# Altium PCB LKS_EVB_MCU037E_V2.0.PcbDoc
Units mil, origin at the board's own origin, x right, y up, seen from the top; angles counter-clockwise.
Board outline 1880 x 1275 mil, 2 copper layers (Top Layer, Bottom Layer); 40 components, 32 nets, 121 pads, 45 vias.
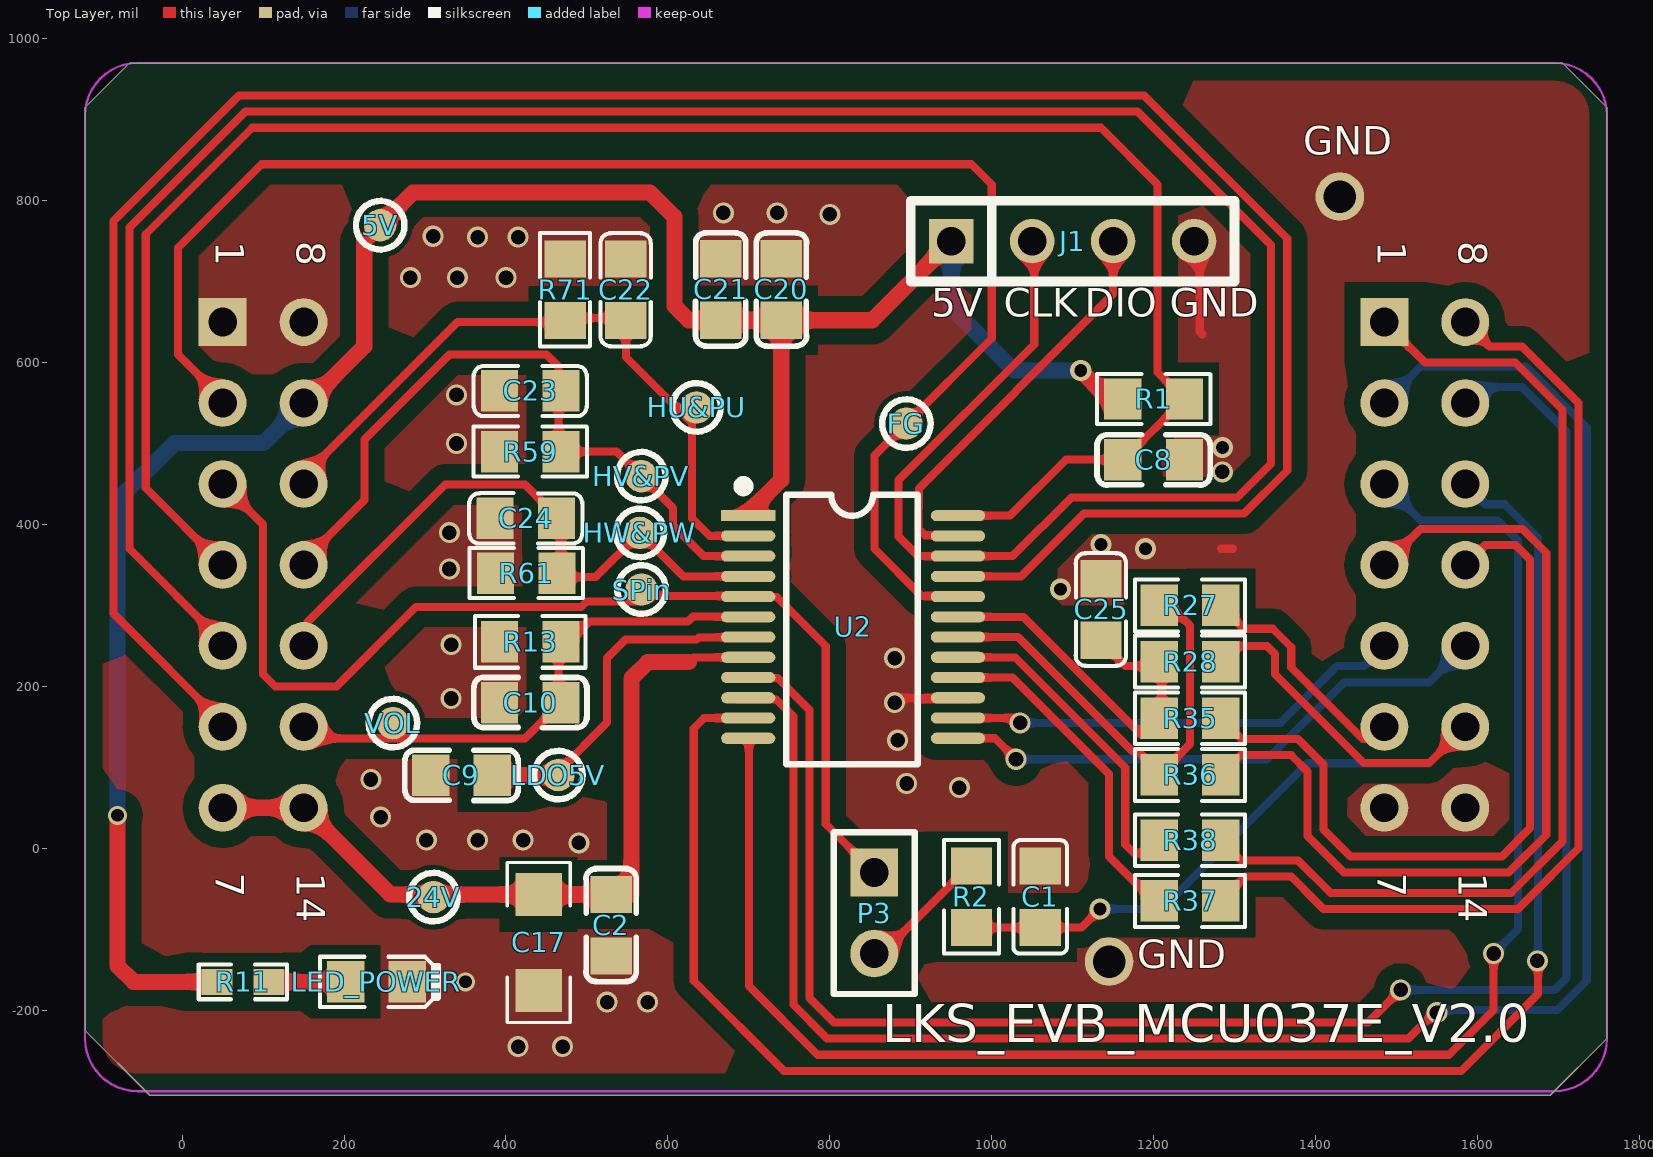
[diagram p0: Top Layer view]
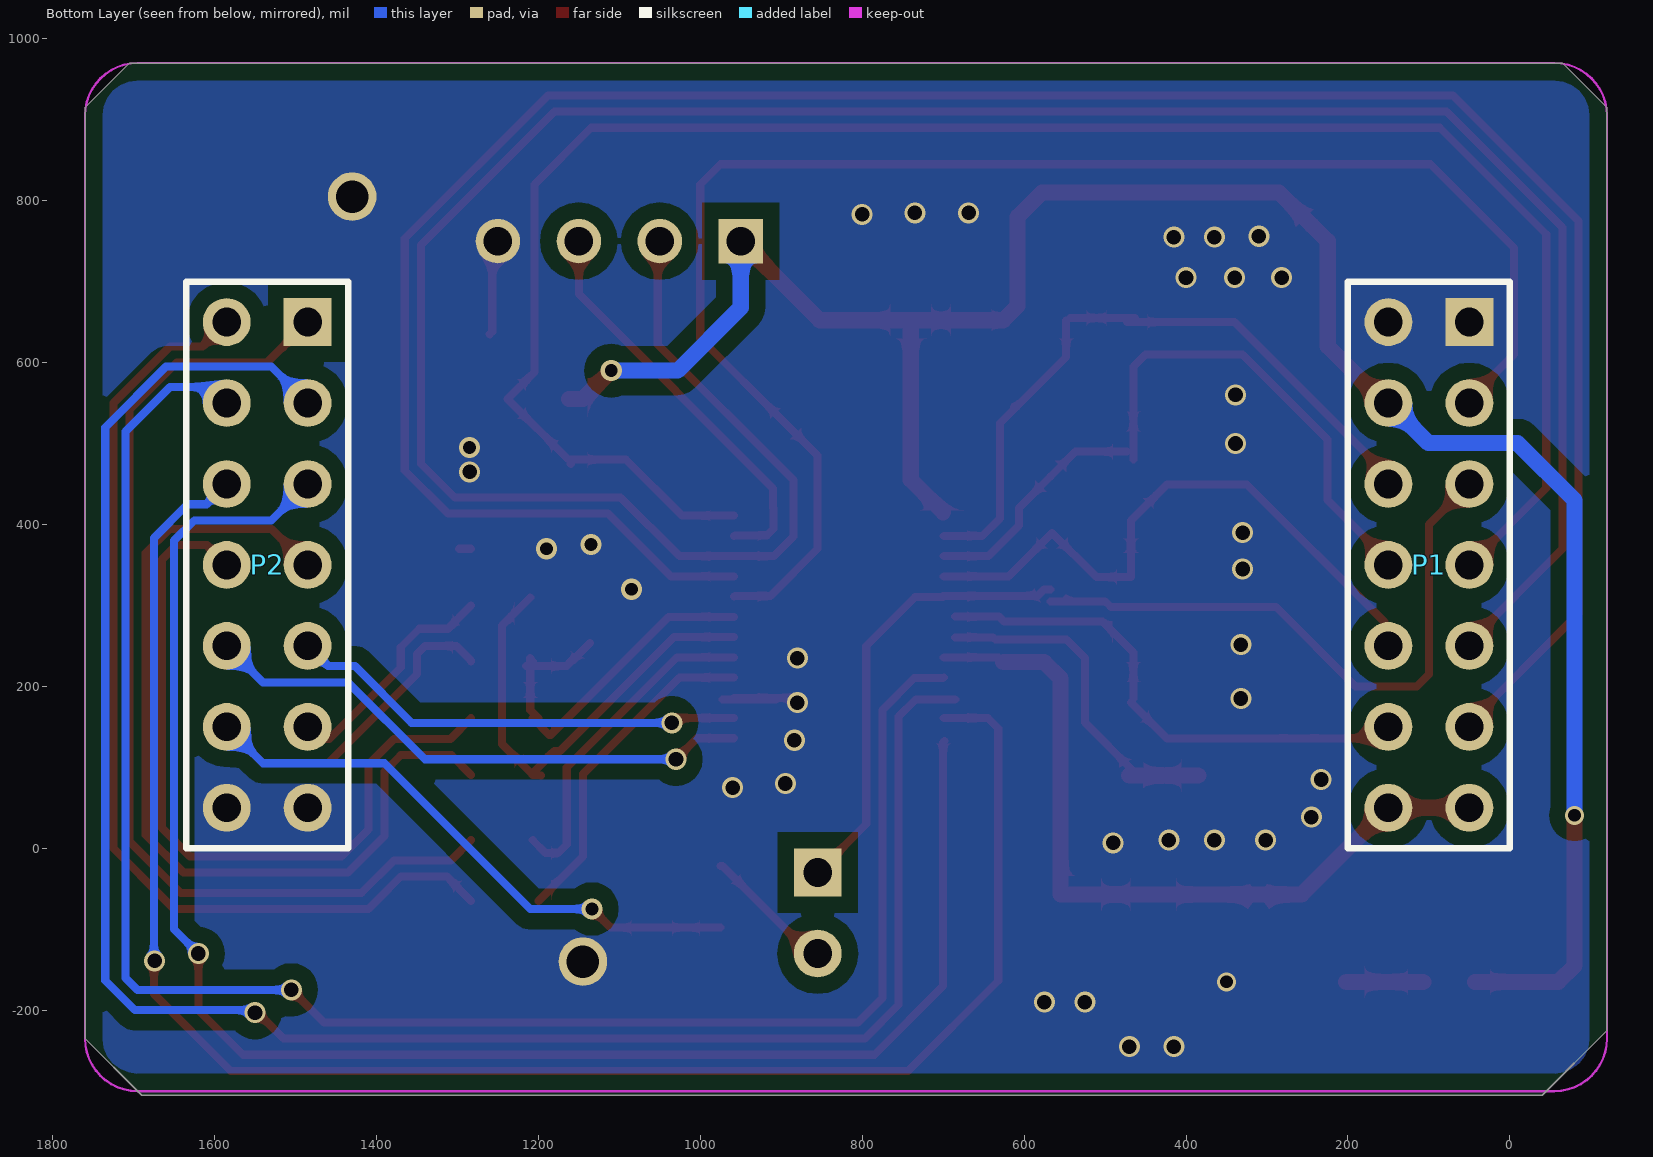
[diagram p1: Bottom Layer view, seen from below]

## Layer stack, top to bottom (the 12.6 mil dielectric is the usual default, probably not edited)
Top Solder: solder mask 0.4, Solder Resist, Dk 3.5
Top Layer: signal copper 1.4
Dielectric1: dielectric 12.6, FR-4, Dk 4.8
Bottom Layer: signal copper 1.4
Bottom Solder: solder mask 0.4, Solder Resist, Dk 3.5

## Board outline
-120,-225 -40,-305 1690,-305 1760,-235 1760,915 1705,970 -65,970 -120,915
cut-out: -3565,-3010 -3555,-3010 -3555,-3000 -3565,-3000

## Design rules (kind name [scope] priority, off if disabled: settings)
Clearance Clearance_1 [INPolygon] p1: gap=20 ignorepadtopadclearanceinfootprint=FALSE except(0: Arc-Hole Track-Hole SMDPad-Hole THPad-Hole Via-Hole Fill-Hole Poly-Hole Region-Hole Text-Hole)
Clearance [All] p2: gap=10 ignorepadtopadclearanceinfootprint=FALSE except(0: Arc-Hole Track-Hole SMDPad-Hole THPad-Hole Via-Hole Fill-Hole Poly-Hole Region-Hole Text-Hole)
ComponentClearance [All] p1: gap=0 collisioncheckmode=3 verticalgap=0 showdistances=FALSE
FabricationTestpoint [(IsPad And (OnTopLayer Or OnBottomLayer))] p1: side=3 testpointundercomponent=TRUE minsize=40 maxsize=100 preferedsize=60 minholesize=0 maxholesize=40 preferedholesize=32 testpointgrid=1 allowsidetop=TRUE allowsidebottom=TRUE usegrid=TRUE gridtolerance=0.01
PolygonConnect [All] p1: connectstyle=Direct reliefconductorwidth=20 reliefentries=4 polygonreliefangle="90 Angle" airgapwidth=10
RoutingVias [All] p1: holewidth=28 width=50 viastyle="Through Hole" minholewidth=28 minwidth=50 maxholewidth=28 maxwidth=50
SilkToSolderMaskClearance SilkscreenOverComponentPads [IsPad] p1: minsilkscreentomaskgap=10 clearancetoexposedcopper=TRUE
SolderMaskExpansion [All] p1: expansion=4 istentingtop=FALSE
Width [All] p1: maxlimit=300 minlimit=1 preferedwidth=10
27 further rules are at their usual default settings.

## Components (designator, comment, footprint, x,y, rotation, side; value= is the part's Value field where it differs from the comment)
5V "TestP" TP-40 245,770 r0 top
24V "TestP" TP-40 310,-60 r90 top
C1 "1nF/50V" 0805C 1060,-60 r270 top (schematic designator C?)
C2 "100nF" 0805C 530,-95 r270 top
C8 "100nF" 0805C 1200,480 r0 top
C9 "1uF/10V" 0805C 345,90 r180 top
C10 "100nF" 0805C 430,180 r180 top
C17 "10uF/50V" 1206 440,-175 r90 top
C20 "100nF" 0805C 740.04,690.32 r90 top
C21 "10uF/10V" 0805C 665.04,690.32 r90 top
C22 "1nF/16V" 0805C 548,690 r270 top
C23 "1nF/16V" 0805C 430,565 r0 top
C24 "1nF/16V" 0805C 424.51,407.59 r0 top
C25 "100pF/50V" 0805C 1135,295 r270 top
FG "TestP" TP-40 895,525 r0 top
HU&PU "TestP" TP-40 635,545 r90 top
HV&PV "TestP" TP-40 566.72,460 r90 top
HW&PW "TestP" TP-40 565,390 r90 top
J1 "SWD" SIP4-2.5 1100,750 r0 top
LDO5V "TestP" TP-40 465,90 r270 top
LED_POWER "" 0805D 240,-165 r0 top
P1 "Header 7X2A" HDR2X7_CEN 50,650 r270 bottom
P2 "Header 7X2A" HDR2X7_CEN 1485,650 r270 bottom
P3 "Header 2" HDR1X2 855,-30 r270 top
R1 "20K" 0805R 1200,555 r0 top
R2 "1K" 0805R 975,-60 r90 top (schematic designator R?)
R11 "3.3K" 0603R 75,-165 r180 top
R13 "3.3K" 0805R 430,255 r180 top
R27 "1K" 0805R 1245,300 r0 top
R28 "1K" 0805R 1245,230.59 r0 top
R35 "1K" 0805R 1245,160.59 r180 top
R36 "1K" 0805R 1245,90.59 r180 top
R37 "1K" 0805R 1245,-65 r180 top
R38 "1K" 0805R 1245,10 r180 top
R59 "3.3K" 0805R 430,490 r0 top
R61 "3.3K" 0805R 425,340 r0 top
R71 "3.3K" 0805R 473,690 r270 top
SPin "TestP" TP-40 567.11,320 r90 top
U2 "037E" SSOP24 828.7,273.39 r0 top
VOL "TestP" TP-40 260,155 r90 top

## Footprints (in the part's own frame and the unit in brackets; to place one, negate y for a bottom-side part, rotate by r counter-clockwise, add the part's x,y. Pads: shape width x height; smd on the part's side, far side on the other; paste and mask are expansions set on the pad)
0603R [mil]
  rect 38x32 smd: 1(-32,0) 2(32,0)
  silkscreen extent -54,-22 54,22, body extent -31,-16 32,16, height 18
0805C [mil]
  rect 46x51.18 smd: 1(-38,0) 2(38,0)
  silkscreen extent -70,-33 70,33, body extent -40,-25 38,25, height 22
0805D [mil]
  rect 46x51.18 smd: 1(-38,0) 2(38,0)
  silkscreen extent -70,-31 77,31, body extent -39,-25 39,25, height 22
0805R [mil]
  rect 46x51.18 smd: 1(-38,0) 2(38,0)
  silkscreen extent -70,-31 70,31, body extent -39,-25 39,25, height 22
1206 [mm]
  rect 1.35x1.45 smd: 1(-0.01,-0.01) 2(2.99,-0.01)
  silkscreen extent -1.02,-1 4,0.98
HDR1X2 [mm] "Connector; Header; 2 Position"
  rect 1.5x1.5 hole 0.9: 1(0,0)
  round 1.5 hole 0.9: 2(2.54,0)
  silkscreen extent -1.27,-1.27 3.81,1.27
HDR2X7_CEN [mm] "Connector; Header; 7x2 Position"
  rect 1.5x1.5 hole 0.9: 1(0,0)
  round 1.5 hole 0.9: 2(2.54,0) 3(5.08,0) 4(7.62,0) 5(10.16,0) 6(12.7,0) 7(15.24,0) 8(0,-2.54) 9(2.54,-2.54) 10(5.08,-2.54) 11(7.62,-2.54) 12(10.16,-2.54) 13(12.7,-2.54) 14(15.24,-2.54)
  silkscreen extent -1.27,-3.81 16.51,1.27
SIP4-2.5 [mil]
  rect 55x55 hole 35: 1(-150,0)
  round 55 hole 35: 2(-50,0) 3(50,0) 4(150,0)
  silkscreen extent -200,-50 200,50
SSOP24 [mil] "8.3*7.8*1.6（蒜米工坊）"
  rect 66.93x13.78 smd: 1(-129.5,137.5)
  oval 66.93x13.78 smd: 2(-129.5,112.5) 3(-129.5,87.5) 4(-129.5,62.5) 5(-129.5,37.5) 6(-129.5,12.5) 7(-129.5,-12.5) 8(-129.5,-37.5) 9(-129.5,-62.5) 10(-129.5,-87.5) 11(-129.5,-112.5) 12(-129.5,-137.5) 13(129.5,-137.5) 14(129.5,-112.5) 15(129.5,-87.5) 16(129.5,-62.5) 17(129.5,-37.5) 18(129.5,-12.5) 19(129.5,12.5) 20(129.5,37.5) 21(129.5,62.5) 22(129.5,87.5) 23(129.5,112.5) 24(129.5,137.5)
  silkscreen extent -140,-170 80,179, body extent -151,-168 152,159, height 65
TP-40 [mil] "测?"
  round 40 smd: 1(-0.39,-0.39)
  silkscreen extent -30,-30 30,30

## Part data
C1 C8 C9 C20 C21 C22 C23 C24 C25: library part C, "Capacitor"
C2 C10 C17: library part CAP, "Capacitor"
J1: library part "Header 4", "Header, 4-Pin"
LED_POWER: library part LED2, "Typical RED, GREEN, YELLOW, AMBER GaAs LED"
P1 P2: "Header, 7-Pin, Dual row"
P3: "Header, 2-Pin"
R1 R2 R27 R28 R35 R36 R37 R38: library part RES2-1
R11 R13: library part Res2, "Resistor"
R59 R61 R71: library part RES/1
U2: library part LKS32MC037EM6S8, "chip"

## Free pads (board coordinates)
  round 60 hole 40: 6(1145,-140) 7(1430,805)

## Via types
v1: diameter 25.98, hole 17.99, Top Layer to Bottom Layer, 37 vias
v2: diameter 26, hole 16, Top Layer to Bottom Layer, 6 vias
v3: diameter 23.62, hole 15.75, Top Layer to Bottom Layer, 2 vias

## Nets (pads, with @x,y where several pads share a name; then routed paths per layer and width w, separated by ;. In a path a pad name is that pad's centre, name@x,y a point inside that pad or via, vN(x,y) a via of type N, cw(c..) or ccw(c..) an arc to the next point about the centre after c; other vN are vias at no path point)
5V: 5V.1 C20.1 C21.1 J1.1 P1.9 R1.1 R11.2 U2.1 | length 2729.4
  Top Layer w20: v3(-80,40.73) -80,-145 -60,-165 R11.2 ; P1.9@155,550 225,620 225,750 5V.1 285,810 578,810 608,780 608,670 625.69,652.32 C21.1 C20.1 852.32,652.32 J1.1 ; U2.1@700,415 740,455 C20.1@740,652 ; v2(1110,590) 1145,555 R1.1
  Bottom Layer w20: v3(-80,40.73) -80,430 -9.53,500.47 100.47,500.47 P1.9 ; J1.1 950,668 1028,590 v2(1110,590)
24V_MCU: 24V.1 C2.1 C17.2 P1.7 P1.14 U2.8 | length 971.2
  Top Layer w10: 625.69,230 631.57,235.89 U2.8
  Top Layer w20: P1.7 P1.14 257,-57 C2.1 555,-57 555,210 575,230 625.69,230
FG: FG.1 P1.2 U2.20 | length 1912.5
  Top Layer w10: P1.2@55,550 -5,610 -5,741.86 98.14,845 975,845 1000,820 1000,630 FG.1 855,485 855,370 913.23,311.77 913.39,311.61 957.48,311.61 U2.20
G0: C1.2 P2.13 R2.1 R28.2 | length 1116.5
  Top Layer w10: R2.1 1110.78,-98 v2(1133.78,-75) ; R28.2 1283,232 1301,250 1340,250 1350,240 1350,215 1459.53,105.47 1540.47,105.47 P2.13
  Bottom Layer w10: v2(1133.78,-75) 1210,-75 1390,105 1540,105 P2.13
G1: P2.4 R36.1 | length 1117.4
  Top Layer w10: R36.1 1307.41,115 1370,115 1390,95 1390,15 1435,-30 1638.43,-30 1685,16.57 1685,365 1655.47,394.53 1529.53,394.53 P2.4
G2: P2.1 R38.1 | length 1273.4
  Top Layer w10: R38.1 1308,-15 1378.28,-15 1418.28,-55 1641.72,-55 1705,8.28 1705,541.72 1646.72,600 1535,600 P2.1
GND: C1.1 C2.2 C8.2 C9.2 C10.2 C17.1 C20.2 C21.2 C22.1 C23.1 C24.1 C25.1 J1.4 LED_POWER.2 P1.1 P1.8 P2.7 P2.14 pad.6 pad.7 R13.2 R59.1 R61.1 R71.1 U2.15 | length 282.8
  Top Layer w10: v1(880.13,180) 884.45,180 890.34,185.89 U2.15 ; 905,185 906.18,183.82 U2.15@972.4,183.82 ; J1.4 1256.94,743.06 1256.94,638.06 1260,635 ; 1283,370 1298.28,370
  other v1: 415,-245 470,-245 525,-190 575,-190 490,6.74 301.58,10 365,10 421.08,10 245.17,38.57 960,75 895,80 233.18,85 883.69,133.45 332.17,185 880,235 332.24,251.63 330,345 330,390 1285,465 338.9,500 338.9,560 281.87,705 340,705 400,705 365,755 415,755 310,756 800,783.04 668.41,785 735,785
  other v2: 1085,320 1190,370 1135,375 1285,495
  other v3: 350,-165
GND0: P2.6 R27.2 | length 291.2
  Top Layer w10: R27.2 1311.82,271.18 1347.1,271.18 1370,248.28 1370,223.28 1458.28,135 1470,135 P2.6
HU&PU: C22.2 HU&PU.1 P1.10 R71.2 U2.2 | length 838.3
  Top Layer w10: P1.10@150,460 340,650 R71.2@473,650 ; R71.2@463,655 C22.2@543,655 ; C22.2 548,607 630,525 630,407.57 651.68,385.89 U2.2
HV&PV: C23.2 HV&PV.1 P1.11 R59.2 U2.3 | length 885.2
  Top Layer w10: P1.11@145,350 225,430 225,505 330,610 450,610 465,595 R59.2@465,480 ; R59.2@473,490 536.72,490 HV&PV.1 606.42,420.29 606.42,398.58 644.11,360.89 U2.3
HW&PW: C24.2 HW&PW.1 P1.12 R61.2 U2.4 | length 785.3
  Top Layer w10: P1.12@155,242 155,279.41 325,449.41 423.59,449.41 468,405 468,335 510.79,335 HW&PW.1 619.11,335.89 U2.4
LDO5V: C9.1 LDO5V.1 U2.7 | length 420.3
  Top Layer w10: LDO5V.1@464.8,95.2 525,155.39 525,235 547.8,257.8 635.3,257.8 638.09,260.59 U2.7@685,260.59
  Top Layer w20: C9.1@385,90 460,90 LDO5V.1@470,90
NetLED_POWER_1: LED_POWER.1 R11.1 | length 95
  Top Layer w20: R11.1 LED_POWER.1
NRST: C8.1 P1.4 R1.2 U2.24 | length 2404.4
  Top Layer w10: P1.4 -45,445 -45,758.43 86.57,890 1135,890 1205,820 1205,588 R1.2 1163,480 C8.1 C8.1@1160,480 ; U2.24 1022.56,410.89 1091.67,480 C8.1@1160,480 ; C8.1@1160,475 C8.1@1160,480
OC: P3.2 R2.2 | length 164.7
  Top Layer w10: P3.2 864.41,-130 972.41,-22 R2.2
OPA2_IN: R38.2 U2.17 | length 411.4
  Top Layer w10: U2.17 1029.11,235.89 1165,100 1165,4.61 1175.46,-5.86 1191.14,-5.86 R38.2
OPA2_IP: R37.2 U2.16 | length 415.7
  Top Layer w10: U2.16 1025.83,210.89 1145,91.72 1145,-10 R37.2@1200,-65
OPA3_IN: R27.1 R36.2 U2.18 | length 580.6
  Top Layer w10: U2.18 1032.4,260.89 1173.28,120 1180.18,120 1207,93.18 R36.2 R36.2@1196.72,90 ; R36.2@1207,90.79 1245,128.79 1245,275 R27.1@1210,310
OPA3_IP: C25.2 R28.1 R35.2 U2.19 | length 496.3
  Top Layer w10: U2.19 1039.4,285.89 1185.14,140.14 1186.55,140.14 R35.2 ; C25.2@1136.45,253.55 1165,225 R28.1@1210,225 ; R35.2@1200,160.59 1210,170.59 R28.1@1210,225 ; R28.1 1215,225 R28.1@1210,225 ; R28.1@1210,235 R28.1@1210,225
RXD: P1.6 U2.21 | length 3018
  Top Layer w10: P1.6@55,150 -85,290 -85,775 70,930 1188.28,930 1365,753.28 1365,466.72 1311.63,413.35 1113.81,413.35 1036.35,335.89 U2.21
SPIN: P1.3 P3.1 SPin.1 U2.5 | length 1334.5
  Top Layer w10: P1.3 100,400 100,215 115,200 190.51,200 288.79,298.28 493,298.28 499.72,305 SPin.1@567.5,305 ; SPin.1 575.62,319.61 583.46,311.77 U2.5@699.92,311.77 ; U2.5 699.92,310.16 734.84,310.16 795,250 795,30 P3.1
SWCLK: J1.2 P1.5 U2.22 | length 3319.7
  Top Layer w10: P1.5@50,255 -65,370 -65,766.72 78.28,910 1180,910 1345,745 1345,475 1303.35,433.35 1098.35,433.35 1025.89,360.89 U2.22 909.11,360.89 885,385 885,455 1052.5,622.5 1052.5,747.5 J1.2
SWDIO: J1.3 U2.23 | length 507
  Top Layer w10: U2.23 957.48,386.61 917.79,386.61 909.74,394.67 909.74,419.95 910,420.22 910,444.61 1150,684.61 J1.3
UH: P2.9 U2.9 | length 2249.5
  Top Layer w10: U2.9 699.92,210.16 735.74,210.16 775,170.9 775,-185 805,-215 1465,-215 v1(1505,-175)
  Bottom Layer w10: v1(1505,-175) 1695,-175 1710,-160 1710,515 1655,570 1605,570 P2.9
UL: P2.2 U2.10 | length 2444.7
  Top Layer w10: U2.10@685,183.82 733.8,183.82 755,162.62 755,-193.28 796.72,-235 835,-235 1515,-235 1547.01,-202.99 v1(1550,-202.99)
  Bottom Layer w10: P2.2 1530,595 1660,595 1735,520 1735,-163.28 1698.28,-200 1552.99,-200 v1(1550,-202.99)
UX: P2.8 R37.1 | length 1233.5
  Top Layer w10: R37.1 1313,-35 1370,-35 1400,-65 1410,-75 1650,-75 1660,-65 1725,0 1725,550 1655,620 1615,620 P2.8
VH: P2.10 U2.11 | length 2194.5
  Top Layer w10: U2.11 644.84,160.89 631.98,148.02 631.98,-163.69 743.28,-275 1580,-275 1675,-180 1675,-140 v1(1674.03,-139.03)
  Bottom Layer w10: P2.10 1610,425 1633.28,425 1675,383.28 1675,-138.06 v1(1674.03,-139.03)
VL: P2.3 U2.12 | length 2067.8
  Top Layer w10: U2.12@698.25,132.64 700,130.89 700,-170 785,-255 1565,-255 1620,-200 v1(1620,-130)
  Bottom Layer w10: P2.3 1530,405 1625,405 1650,380 1650,-100 v1(1620,-130)
VOL: C10.1 P1.13 R13.1 U2.6 VOL.1 | length 639.7
  Top Layer w10: P1.13@150,155 169.41,135.59 423.59,135.59 C10.1 ; C10.1@465,185 465,242 503,280 625,280 631.18,286.18 U2.6@685,286.18
VX: P2.11 R35.1 | length 943.4
  Top Layer w10: R35.1 1308.59,135 1378.28,135 1410,103.28 1410,23.28 1443.28,-10 1630.15,-10 1665,24.85 1665,356.72 1647.19,374.53 1609.53,374.53 P2.11
WH: P2.12 U2.13 | length 695.5
  Top Layer w10: U2.13 1004.11,135.89 v1(1030,110)
  Bottom Layer w10: v1(1030,110) 1340,110 1435,205 1540,205 P2.12
WL: P2.5 U2.14 | length 568.6
  Top Layer w10: U2.14 1024.79,160.89 1030.67,155 v1(1035,155)
  Bottom Layer w10: v1(1035,155) 1356.72,155 1426.72,225 1460,225 P2.5

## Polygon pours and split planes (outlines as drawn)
GND on Top Layer "Bottom Layer-No Net" (solid, remove dead copper, pour order 3): -125,970 -125,-300 1750,-300 1755,-295 1755,970
GND on Bottom Layer "Bottom Layer-No Net" (solid, remove dead copper, pour order 4): -120,970 -120,-300 1755,-300 1760,-295 1760,970

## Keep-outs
Keep-Out Layer:
  lines w2.99: -120,-235 ccw(c-55,-235) -55,-300 ; -120,905 cw(c-55,905) -55,970 ; 1695,-300 ccw(c1695,-235) 1760,-235 ; 1695,970 cw(c1695,905) 1760,905
  lines w3: -120,-235 -120,905 ; -55,-300 1695,-300 ; -55,970 1695,970 ; 1760,-235 1760,905

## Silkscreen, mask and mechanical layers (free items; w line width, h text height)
Top Overlay:
  text "GND" at 1385,845 h60
  text "5V" at 925,645 h60
  text "CLK" at 1015,645 h60
  text "DIO" at 1115,645 h60
  text "GND" at 1220,645 h60
  text "GND" at 1180,-160 h60
  text "LKS_EVB_MCU037E_V2.0" at 865,-255 h80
